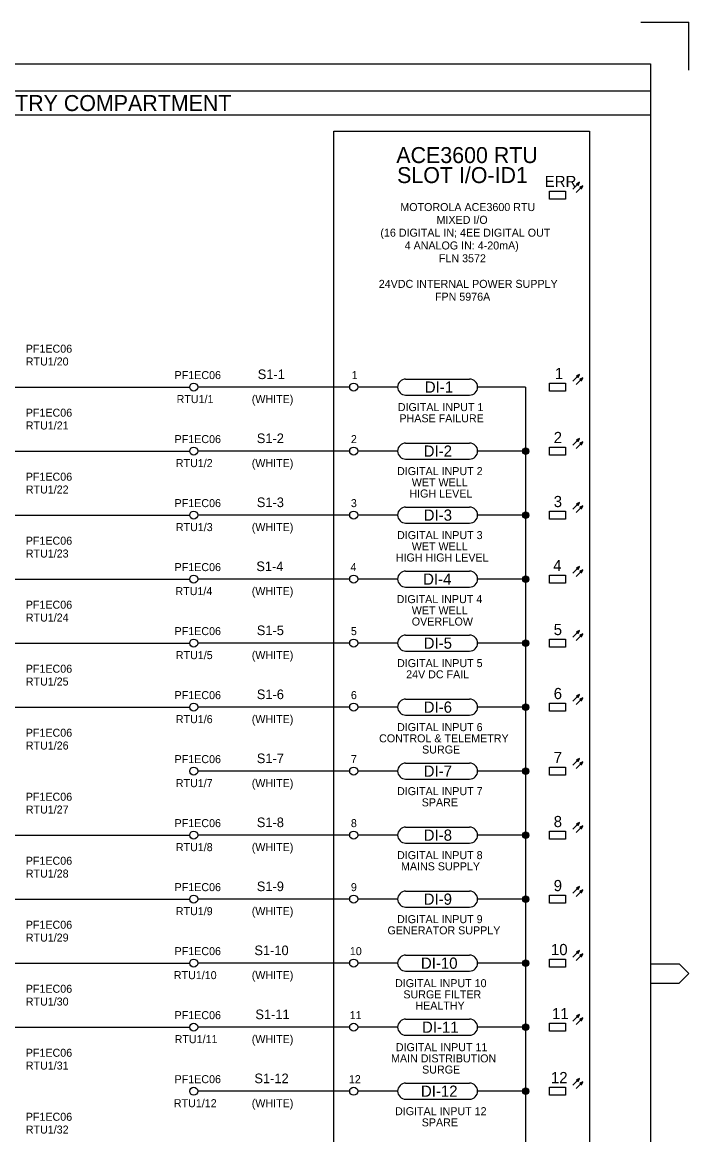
# Model space of a CAD drawing. Extents: x 0 to 841, y 0 to 594.
# Drawn here: x 632.6 to 841, y 246.4 to 594 of the extents above; entities that cross this region are included whole.
import ezdxf

# ---------------------------------------------------------------- set-up
doc = ezdxf.new("R2010")
doc.units = 0
for name, color, linetype in [('A1BORDER', 7, 'Continuous'), ('Level 1', 7, 'Continuous'), ('Level 10', 7, 'Continuous'), ('Level 2', 7, 'Continuous')]:
    doc.layers.add(name, color=color, linetype=linetype)

msp = doc.modelspace()

# ---------------------------------------------------------------- linework, layer by layer
at = {"layer": 'A1BORDER'}
for p, q in [((826, 594), (841, 594)), ((841, 579), (841, 594)), ((28, 581), (829, 581)), ((829, 581), (829, 15)), ((829, 299.76), (838, 299.76)), ((838, 299.76), (841, 296.76)), ((838, 293.76), (841, 296.76)), ((829, 293.76), (838, 293.76))]:
    msp.add_line(p, q, dxfattribs=at)
at = {"layer": 'Level 1'}
for p, q in [((829, 572.5), (160, 572.5)), ((829, 565), (160, 565)), ((530, 480), (685, 480)), ((735, 480), (687.5, 480)), ((750, 480), (737.5, 480)), ((752.5, 482.5), (772.5, 482.5)), ((790, 480), (775, 480)), ((790, 480), (790, 140)), ((752.5, 477.5), (772.5, 477.5)), ((752.5, 462.5), (772.5, 462.5)), ((280, 460), (685, 460)), ((735, 460), (687.5, 460)), ((750, 460), (737.5, 460)), ((790, 460), (775, 460)), ((752.5, 457.5), (772.5, 457.5)), ((752.5, 442.5), (772.5, 442.5)), ((280, 440), (685, 440)), ((735, 440), (687.5, 440)), ((750, 440), (737.5, 440)), ((790, 440), (775, 440)), ((752.5, 437.5), (772.5, 437.5)), ((752.5, 422.5), (772.5, 422.5)), ((280, 420), (685, 420)), ((735, 420), (687.5, 420)), ((750, 420), (737.5, 420)), ((752.5, 417.5), (772.5, 417.5)), ((790, 420), (775, 420)), ((530, 400), (685, 400)), ((735, 400), (687.5, 400)), ((750, 400), (737.5, 400)), ((752.5, 402.5), (772.5, 402.5)), ((790, 400), (775, 400)), ((752.5, 397.5), (772.5, 397.5)), ((752.5, 382.5), (772.5, 382.5)), ((415, 380), (685, 380)), ((735, 380), (687.5, 380)), ((750, 380), (737.5, 380)), ((790, 380), (775, 380)), ((752.5, 377.5), (772.5, 377.5)), ((752.5, 362.5), (772.5, 362.5)), ((735, 360), (687.5, 360)), ((750, 360), (737.5, 360)), ((790, 360), (775, 360)), ((752.5, 357.5), (772.5, 357.5)), ((752.5, 342.5), (772.5, 342.5)), ((360, 340), (685, 340)), ((735, 340), (687.5, 340)), ((750, 340), (737.5, 340)), ((752.5, 337.5), (772.5, 337.5)), ((790, 340), (775, 340)), ((360, 320), (685, 320)), ((735, 320), (687.5, 320)), ((750, 320), (737.5, 320)), ((752.5, 322.5), (772.5, 322.5)), ((790, 320), (775, 320)), ((752.5, 317.5), (772.5, 317.5)), ((752.5, 302.5), (772.5, 302.5)), ((480, 300), (685, 300)), ((735, 300), (687.5, 300)), ((750, 300), (737.5, 300)), ((790, 300), (775, 300)), ((752.5, 297.5), (772.5, 297.5)), ((752.5, 282.5), (772.5, 282.5)), ((325, 280), (685, 280)), ((735, 280), (687.5, 280)), ((750, 280), (737.5, 280)), ((790, 280), (775, 280)), ((752.5, 277.5), (772.5, 277.5)), ((752.5, 262.5), (772.5, 262.5)), ((735, 260), (687.5, 260)), ((750, 260), (737.5, 260)), ((752.5, 257.5), (772.5, 257.5)), ((790, 260), (775, 260))]:
    msp.add_line(p, q, dxfattribs=at)
msp.add_lwpolyline([(730, 96.05), (730, 560), (810, 560), (810, 103.95)], dxfattribs=at)
for points in [[(797.5, 541.25), (802.5, 541.25), (802.5, 538.75), (797.5, 538.75)], [(797.5, 481.25), (802.5, 481.25), (802.5, 478.75), (797.5, 478.75)], [(797.5, 461.25), (802.5, 461.25), (802.5, 458.75), (797.5, 458.75)], [(797.5, 441.25), (802.5, 441.25), (802.5, 438.75), (797.5, 438.75)], [(797.5, 421.25), (802.5, 421.25), (802.5, 418.75), (797.5, 418.75)], [(797.5, 401.25), (802.5, 401.25), (802.5, 398.75), (797.5, 398.75)], [(797.5, 381.25), (802.5, 381.25), (802.5, 378.75), (797.5, 378.75)], [(797.5, 361.25), (802.5, 361.25), (802.5, 358.75), (797.5, 358.75)], [(797.5, 341.25), (802.5, 341.25), (802.5, 338.75), (797.5, 338.75)], [(797.5, 321.25), (802.5, 321.25), (802.5, 318.75), (797.5, 318.75)], [(797.5, 301.25), (802.5, 301.25), (802.5, 298.75), (797.5, 298.75)], [(797.5, 281.25), (802.5, 281.25), (802.5, 278.75), (797.5, 278.75)], [(797.5, 261.25), (802.5, 261.25), (802.5, 258.75), (797.5, 258.75)]]:
    msp.add_lwpolyline(points, close=True, dxfattribs=at)
for centre, start, end in [((752.5, 480), 90, 270), ((772.5, 480), 270, 90), ((752.5, 460), 90, 270), ((772.5, 460), 270, 90), ((752.5, 440), 90, 270), ((772.5, 440), 270, 90), ((752.5, 420), 90, 270), ((772.5, 420), 270, 90), ((752.5, 400), 90, 270), ((772.5, 400), 270, 90), ((752.5, 380), 90, 270), ((772.5, 380), 270, 90), ((752.5, 360), 90, 270), ((772.5, 360), 270, 90), ((752.5, 340), 90, 270), ((772.5, 340), 270, 90), ((752.5, 320), 90, 270), ((772.5, 320), 270, 90), ((752.5, 300), 90, 270), ((772.5, 300), 270, 90), ((752.5, 280), 90, 270), ((772.5, 280), 270, 90), ((752.5, 260), 90, 270), ((772.5, 260), 270, 90)]:
    msp.add_arc(centre, 2.5, start, end, dxfattribs=at)
at = {"layer": 'Level 10'}
for p, q in [((804.73, 541.86), (806.86, 543.98)), ((805.79, 540.79), (807.91, 542.92)), ((805.96, 543.58), (806.67, 543.58)), ((806, 543.42), (806.61, 543.42)), ((806.14, 543.27), (806.53, 543.27)), ((806.29, 543.73), (806.74, 543.73)), ((806.3, 543.12), (806.47, 543.12)), ((806.62, 543.88), (806.81, 543.88)), ((807.02, 542.51), (807.73, 542.51)), ((807.06, 542.37), (807.66, 542.37)), ((807.35, 542.66), (807.8, 542.66)), ((807.68, 542.82), (807.87, 542.82)), ((807.21, 542.22), (807.6, 542.22)), ((807.36, 542.07), (807.53, 542.07)), ((804.73, 481.86), (806.86, 483.98)), ((805.96, 483.57), (806.67, 483.57)), ((806, 483.43), (806.61, 483.43)), ((806.14, 483.28), (806.53, 483.28)), ((806.29, 483.73), (806.74, 483.73)), ((806.62, 483.88), (806.81, 483.88)), ((805.79, 480.8), (807.91, 482.92)), ((806.3, 483.12), (806.47, 483.12)), ((807.02, 482.51), (807.73, 482.51)), ((807.06, 482.37), (807.66, 482.37)), ((807.21, 482.22), (807.6, 482.22)), ((807.35, 482.67), (807.8, 482.67)), ((807.36, 482.06), (807.53, 482.06)), ((807.68, 482.81), (807.87, 482.81)), ((804.73, 461.86), (806.86, 463.98)), ((805.79, 460.8), (807.91, 462.92)), ((805.96, 463.57), (806.67, 463.57)), ((806, 463.43), (806.61, 463.43)), ((806.14, 463.28), (806.53, 463.28)), ((806.29, 463.73), (806.74, 463.73)), ((806.3, 463.12), (806.47, 463.12)), ((806.62, 463.88), (806.81, 463.88)), ((807.02, 462.51), (807.73, 462.51)), ((807.06, 462.37), (807.66, 462.37)), ((807.35, 462.67), (807.8, 462.67)), ((807.68, 462.81), (807.87, 462.81)), ((789.01, 460.1), (790.99, 460.1)), ((789.02, 459.8), (790.98, 459.8)), ((789.08, 460.4), (790.92, 460.4)), ((789.13, 459.5), (790.87, 459.5)), ((789.29, 460.7), (790.71, 460.7)), ((789.4, 459.2), (790.6, 459.2)), ((790, 461), (790, 461)), ((807.21, 462.22), (807.6, 462.22)), ((807.36, 462.06), (807.53, 462.06)), ((804.73, 441.86), (806.86, 443.98)), ((805.79, 440.8), (807.91, 442.92)), ((805.96, 443.57), (806.67, 443.57)), ((806, 443.43), (806.61, 443.43)), ((806.14, 443.28), (806.53, 443.28)), ((806.29, 443.73), (806.74, 443.73)), ((806.3, 443.12), (806.47, 443.12)), ((806.62, 443.88), (806.81, 443.88)), ((807.02, 442.51), (807.73, 442.51)), ((807.06, 442.37), (807.66, 442.37)), ((807.21, 442.22), (807.6, 442.22)), ((807.35, 442.67), (807.8, 442.67)), ((807.36, 442.06), (807.53, 442.06)), ((807.68, 442.81), (807.87, 442.81)), ((789.01, 440.1), (790.99, 440.1)), ((789.02, 439.8), (790.98, 439.8)), ((789.08, 440.4), (790.92, 440.4)), ((789.13, 439.5), (790.87, 439.5)), ((789.29, 440.7), (790.71, 440.7)), ((789.4, 439.2), (790.6, 439.2)), ((790, 441), (790, 441)), ((789.29, 420.7), (790.71, 420.7)), ((790, 421), (790, 421)), ((804.73, 421.86), (806.86, 423.98)), ((805.79, 420.8), (807.91, 422.92)), ((805.96, 423.57), (806.67, 423.57)), ((806, 423.43), (806.61, 423.43)), ((806.14, 423.28), (806.53, 423.28)), ((806.29, 423.73), (806.74, 423.73)), ((806.3, 423.12), (806.47, 423.12)), ((806.62, 423.88), (806.81, 423.88)), ((807.02, 422.51), (807.73, 422.51)), ((807.06, 422.37), (807.66, 422.37)), ((807.21, 422.22), (807.6, 422.22)), ((807.35, 422.67), (807.8, 422.67)), ((807.36, 422.06), (807.53, 422.06)), ((807.68, 422.81), (807.87, 422.81)), ((789.01, 420.1), (790.99, 420.1)), ((789.02, 419.8), (790.98, 419.8)), ((789.08, 420.4), (790.92, 420.4)), ((789.13, 419.5), (790.87, 419.5)), ((789.4, 419.2), (790.6, 419.2)), ((804.73, 401.86), (806.86, 403.98)), ((805.96, 403.57), (806.67, 403.57)), ((806, 403.43), (806.61, 403.43)), ((806.14, 403.28), (806.53, 403.28)), ((806.29, 403.73), (806.74, 403.73)), ((806.62, 403.88), (806.81, 403.88)), ((789.01, 400.1), (790.99, 400.1)), ((789.02, 399.8), (790.98, 399.8)), ((789.08, 400.4), (790.92, 400.4)), ((789.29, 400.7), (790.71, 400.7)), ((790, 401), (790, 401)), ((805.79, 400.8), (807.91, 402.92)), ((806.3, 403.12), (806.47, 403.12)), ((807.02, 402.51), (807.73, 402.51)), ((807.06, 402.37), (807.66, 402.37)), ((807.21, 402.22), (807.6, 402.22)), ((807.35, 402.67), (807.8, 402.67)), ((807.36, 402.06), (807.53, 402.06)), ((807.68, 402.81), (807.87, 402.81)), ((789.13, 399.5), (790.87, 399.5)), ((789.4, 399.2), (790.6, 399.2)), ((804.73, 381.86), (806.86, 383.98)), ((805.79, 380.8), (807.91, 382.92)), ((805.96, 383.57), (806.67, 383.57)), ((806, 383.43), (806.61, 383.43)), ((806.14, 383.28), (806.53, 383.28)), ((806.29, 383.73), (806.74, 383.73)), ((806.3, 383.12), (806.47, 383.12)), ((806.62, 383.88), (806.81, 383.88)), ((807.02, 382.51), (807.73, 382.51)), ((807.35, 382.67), (807.8, 382.67)), ((807.68, 382.81), (807.87, 382.81)), ((789.01, 380.1), (790.99, 380.1)), ((789.02, 379.8), (790.98, 379.8)), ((789.08, 380.4), (790.92, 380.4)), ((789.13, 379.5), (790.87, 379.5)), ((789.29, 380.7), (790.71, 380.7)), ((789.4, 379.2), (790.6, 379.2)), ((790, 381), (790, 381)), ((807.06, 382.37), (807.66, 382.37)), ((807.21, 382.22), (807.6, 382.22)), ((807.36, 382.06), (807.53, 382.06)), ((804.73, 361.86), (806.86, 363.98)), ((805.79, 360.8), (807.91, 362.92)), ((805.96, 363.57), (806.67, 363.57)), ((806, 363.43), (806.61, 363.43)), ((806.14, 363.28), (806.53, 363.28)), ((806.29, 363.73), (806.74, 363.73)), ((806.3, 363.12), (806.47, 363.12)), ((806.62, 363.88), (806.81, 363.88)), ((807.02, 362.51), (807.73, 362.51)), ((807.06, 362.37), (807.66, 362.37)), ((807.21, 362.22), (807.6, 362.22)), ((807.35, 362.67), (807.8, 362.67)), ((807.36, 362.06), (807.53, 362.06)), ((807.68, 362.81), (807.87, 362.81)), ((789.01, 360.1), (790.99, 360.1)), ((789.02, 359.8), (790.98, 359.8)), ((789.08, 360.4), (790.92, 360.4)), ((789.13, 359.5), (790.87, 359.5)), ((789.29, 360.7), (790.71, 360.7)), ((789.4, 359.2), (790.6, 359.2)), ((790, 361), (790, 361)), ((789.29, 340.7), (790.71, 340.7)), ((790, 341), (790, 341)), ((804.73, 341.86), (806.86, 343.98)), ((805.79, 340.8), (807.91, 342.92)), ((805.96, 343.57), (806.67, 343.57)), ((806, 343.43), (806.61, 343.43)), ((806.14, 343.28), (806.53, 343.28)), ((806.29, 343.73), (806.74, 343.73)), ((806.3, 343.12), (806.47, 343.12)), ((806.62, 343.88), (806.81, 343.88)), ((807.02, 342.51), (807.73, 342.51)), ((807.06, 342.37), (807.66, 342.37)), ((807.21, 342.22), (807.6, 342.22)), ((807.35, 342.67), (807.8, 342.67)), ((807.36, 342.06), (807.53, 342.06)), ((807.68, 342.81), (807.87, 342.81)), ((789.01, 340.1), (790.99, 340.1)), ((789.02, 339.8), (790.98, 339.8)), ((789.08, 340.4), (790.92, 340.4)), ((789.13, 339.5), (790.87, 339.5)), ((789.4, 339.2), (790.6, 339.2)), ((804.73, 321.86), (806.86, 323.98)), ((805.96, 323.57), (806.67, 323.57)), ((806, 323.43), (806.61, 323.43)), ((806.29, 323.73), (806.74, 323.73)), ((806.62, 323.88), (806.81, 323.88)), ((789.01, 320.1), (790.99, 320.1)), ((789.08, 320.4), (790.92, 320.4)), ((789.29, 320.7), (790.71, 320.7)), ((790, 321), (790, 321)), ((805.79, 320.8), (807.91, 322.92)), ((806.14, 323.28), (806.53, 323.28)), ((806.3, 323.12), (806.47, 323.12)), ((807.02, 322.51), (807.73, 322.51)), ((807.06, 322.37), (807.66, 322.37)), ((807.21, 322.22), (807.6, 322.22)), ((807.35, 322.67), (807.8, 322.67)), ((807.36, 322.06), (807.53, 322.06)), ((807.68, 322.81), (807.87, 322.81)), ((789.02, 319.8), (790.98, 319.8)), ((789.13, 319.5), (790.87, 319.5)), ((789.4, 319.2), (790.6, 319.2)), ((804.73, 301.86), (806.86, 303.98)), ((805.79, 300.8), (807.91, 302.92)), ((805.96, 303.57), (806.67, 303.57)), ((806, 303.43), (806.61, 303.43)), ((806.14, 303.28), (806.53, 303.28)), ((806.29, 303.73), (806.74, 303.73)), ((806.3, 303.12), (806.47, 303.12)), ((806.62, 303.88), (806.81, 303.88)), ((807.02, 302.51), (807.73, 302.51)), ((807.35, 302.67), (807.8, 302.67)), ((807.68, 302.81), (807.87, 302.81)), ((789.01, 300.1), (790.99, 300.1)), ((789.02, 299.8), (790.98, 299.8)), ((789.08, 300.4), (790.92, 300.4)), ((789.13, 299.5), (790.87, 299.5)), ((789.29, 300.7), (790.71, 300.7)), ((789.4, 299.2), (790.6, 299.2)), ((790, 301), (790, 301)), ((807.06, 302.37), (807.66, 302.37)), ((807.21, 302.22), (807.6, 302.22)), ((807.36, 302.06), (807.53, 302.06)), ((804.73, 281.86), (806.86, 283.98)), ((805.79, 280.8), (807.91, 282.92)), ((805.96, 283.57), (806.67, 283.57)), ((806, 283.43), (806.61, 283.43)), ((806.14, 283.28), (806.53, 283.28)), ((806.29, 283.73), (806.74, 283.73)), ((806.3, 283.12), (806.47, 283.12)), ((806.62, 283.88), (806.81, 283.88)), ((807.02, 282.51), (807.73, 282.51)), ((807.06, 282.37), (807.66, 282.37)), ((807.21, 282.22), (807.6, 282.22)), ((807.35, 282.67), (807.8, 282.67)), ((807.36, 282.06), (807.53, 282.06)), ((807.68, 282.81), (807.87, 282.81)), ((789.01, 280.1), (790.99, 280.1)), ((789.02, 279.8), (790.98, 279.8)), ((789.08, 280.4), (790.92, 280.4)), ((789.13, 279.5), (790.87, 279.5)), ((789.29, 280.7), (790.71, 280.7)), ((789.4, 279.2), (790.6, 279.2)), ((790, 281), (790, 281)), ((790, 261), (790, 261)), ((804.73, 261.86), (806.86, 263.98)), ((805.79, 260.8), (807.91, 262.92)), ((805.96, 263.57), (806.67, 263.57)), ((806, 263.43), (806.61, 263.43)), ((806.14, 263.27), (806.53, 263.27)), ((806.29, 263.73), (806.74, 263.73)), ((806.3, 263.12), (806.47, 263.12)), ((806.62, 263.88), (806.81, 263.88)), ((807.02, 262.51), (807.73, 262.51)), ((807.06, 262.37), (807.66, 262.37)), ((807.21, 262.22), (807.6, 262.22)), ((807.35, 262.67), (807.8, 262.67)), ((807.36, 262.06), (807.53, 262.06)), ((807.68, 262.81), (807.87, 262.81)), ((789.01, 260.1), (790.99, 260.1)), ((789.02, 259.8), (790.98, 259.8)), ((789.08, 260.4), (790.92, 260.4)), ((789.13, 259.5), (790.87, 259.5)), ((789.29, 260.7), (790.71, 260.7)), ((789.4, 259.2), (790.6, 259.2))]:
    msp.add_line(p, q, dxfattribs=at)
for points in [[(806.86, 543.98), (805.88, 543.54), (806.41, 543)], [(807.91, 542.92), (806.94, 542.48), (807.48, 541.95)], [(806.86, 483.98), (805.88, 483.54), (806.41, 483)], [(807.91, 482.92), (806.94, 482.48), (807.48, 481.94)], [(806.86, 463.98), (805.88, 463.54), (806.41, 463)], [(807.91, 462.92), (806.94, 462.48), (807.48, 461.94)], [(806.86, 443.98), (805.88, 443.54), (806.41, 443)], [(807.91, 442.92), (806.94, 442.48), (807.48, 441.94)], [(806.86, 423.98), (805.88, 423.54), (806.41, 423)], [(807.91, 422.92), (806.94, 422.48), (807.48, 421.94)], [(806.86, 403.98), (805.88, 403.54), (806.41, 403)], [(807.91, 402.92), (806.94, 402.48), (807.48, 401.94)], [(806.86, 383.98), (805.88, 383.54), (806.41, 383)], [(807.91, 382.92), (806.94, 382.48), (807.48, 381.94)], [(806.86, 363.98), (805.88, 363.54), (806.41, 363)], [(807.91, 362.92), (806.94, 362.48), (807.48, 361.94)], [(806.86, 343.98), (805.88, 343.54), (806.41, 343)], [(807.91, 342.92), (806.94, 342.48), (807.48, 341.94)], [(806.86, 323.98), (805.88, 323.54), (806.41, 323)], [(807.91, 322.92), (806.94, 322.48), (807.48, 321.94)], [(806.86, 303.98), (805.88, 303.54), (806.41, 303)], [(807.91, 302.92), (806.94, 302.48), (807.48, 301.94)], [(806.86, 283.98), (805.88, 283.54), (806.41, 283)], [(807.91, 282.92), (806.94, 282.48), (807.48, 281.94)], [(806.86, 263.98), (805.88, 263.54), (806.41, 263)], [(807.91, 262.92), (806.94, 262.48), (807.48, 261.94)]]:
    msp.add_lwpolyline(points, close=True, dxfattribs=at)
for centre, radius in [((686.25, 480), 1.25), ((736.25, 480), 1.25), ((686.25, 460), 1.25), ((736.25, 460), 1.25), ((790, 460), 1), ((686.25, 440), 1.25), ((736.25, 440), 1.25), ((790, 440), 1), ((686.25, 420), 1.25), ((736.25, 420), 1.25), ((790, 420), 1), ((686.25, 400), 1.25), ((736.25, 400), 1.25), ((790, 400), 1), ((686.25, 380), 1.25), ((736.25, 380), 1.25), ((790, 380), 1), ((686.25, 360), 1.25), ((736.25, 360), 1.25), ((790, 360), 1), ((686.25, 340), 1.25), ((736.25, 340), 1.25), ((790, 340), 1), ((686.25, 320), 1.25), ((736.25, 320), 1.25), ((790, 320), 1), ((686.25, 300), 1.25), ((736.25, 300), 1.25), ((790, 300), 1), ((686.25, 280), 1.25), ((736.25, 280), 1.25), ((790, 280), 1), ((686.25, 260), 1.25), ((736.25, 260), 1.25), ((790, 260), 1)]:
    msp.add_circle(centre, radius, dxfattribs=at)

# ---------------------------------------------------------------- texts
at = {"layer": 'Level 1'}
for s, height, p in [('TELEMETRY COMPARTMENT', 5, (603.66, 566.25)), ('ACE3600 RTU', 5, (749.58, 550)), ('SLOT I/O-ID1', 5, (749.83, 543.75)), ('ERR', 3.5, (795.99, 542.5)), ('MOTOROLA ACE3600 RTU', 2.5, (750.83, 535)), ('MIXED I/O', 2.5, (762.16, 531)), ('(16 DIGITAL IN; 4EE DIGITAL OUT', 2.5, (744.6, 527)), ('4 ANALOG IN: 4-20mA)', 2.5, (752.19, 523)), ('FLN 3572', 2.5, (762.9, 519)), ('24VDC INTERNAL POWER SUPPLY', 2.5, (744.1, 511)), ('FPN 5976A', 2.5, (761.66, 507)), ('PF1EC06', 2.5, (680.27, 482.5)), ('S1-1', 3, (706.26, 482.5)), ('1', 2.5, (735.63, 482.5)), ('1', 3.5, (799.13, 482.5)), ('DI-1', 3.5, (758.49, 478.25)), ('RTU1/1', 2.5, (680.9, 475)), ('(WHITE)', 2.5, (704.39, 475)), ('PF1EC06', 2.5, (633.75, 470.75)), ('DIGITAL INPUT 1', 2.5, (750.05, 472.5)), ('RTU1/21', 2.5, (633.75, 466.75)), ('PHASE FAILURE', 2.5, (750.55, 469)), ('2', 3.5, (798.78, 462.5)), ('PF1EC06', 2.5, (680.27, 462.5)), ('S1-2', 3, (705.97, 462.5)), ('2', 2.5, (735.38, 462.5)), ('DI-2', 3.5, (758.14, 458.25)), ('RTU1/2', 2.5, (680.65, 455)), ('(WHITE)', 2.5, (704.39, 455)), ('PF1EC06', 2.5, (633.75, 450.75)), ('DIGITAL INPUT 2', 2.5, (749.8, 452.5)), ('RTU1/22', 2.5, (633.75, 446.75)), ('WET WELL', 2.5, (754.41, 449)), ('PF1EC06', 2.5, (680.27, 442.5)), ('S1-3', 3, (705.97, 442.5)), ('3', 2.5, (735.38, 442.5)), ('HIGH LEVEL', 2.5, (753.66, 445.5)), ('3', 3.5, (798.78, 442.5)), ('DI-3', 3.5, (758.14, 438.25)), ('RTU1/3', 2.5, (680.65, 435)), ('(WHITE)', 2.5, (704.39, 435)), ('DIGITAL INPUT 3', 2.5, (749.8, 432.5)), ('PF1EC06', 2.5, (633.75, 430.75)), ('WET WELL', 2.5, (754.41, 429)), ('RTU1/23', 2.5, (633.75, 426.75)), ('HIGH HIGH LEVEL', 2.5, (749.43, 425.5)), ('PF1EC06', 2.5, (680.27, 422.5)), ('S1-4', 3, (705.82, 422.5)), ('4', 2.5, (735.25, 422.5)), ('4', 3.5, (798.61, 422.5)), ('DI-4', 3.5, (757.97, 418.25)), ('RTU1/4', 2.5, (680.53, 415)), ('(WHITE)', 2.5, (704.39, 415)), ('DIGITAL INPUT 4', 2.5, (749.68, 412.5)), ('PF1EC06', 2.5, (633.75, 410.75)), ('WET WELL', 2.5, (754.41, 409)), ('RTU1/24', 2.5, (633.75, 406.75)), ('OVERFLOW', 2.5, (754.41, 405.5)), ('PF1EC06', 2.5, (680.27, 402.5)), ('S1-5', 3, (705.97, 402.5)), ('5', 2.5, (735.38, 402.5)), ('5', 3.5, (798.78, 402.5)), ('DI-5', 3.5, (758.14, 398.25)), ('RTU1/5', 2.5, (680.65, 395)), ('(WHITE)', 2.5, (704.39, 395)), ('PF1EC06', 2.5, (633.75, 390.75)), ('DIGITAL INPUT 5', 2.5, (749.8, 392.5)), ('RTU1/25', 2.5, (633.75, 386.75)), ('24V DC FAIL', 2.5, (752.66, 389)), ('6', 3.5, (798.78, 382.5)), ('PF1EC06', 2.5, (680.27, 382.5)), ('S1-6', 3, (705.97, 382.5)), ('6', 2.5, (735.38, 382.5)), ('DI-6', 3.5, (758.14, 378.25)), ('RTU1/6', 2.5, (680.65, 375)), ('(WHITE)', 2.5, (704.39, 375)), ('PF1EC06', 2.5, (633.75, 370.75)), ('DIGITAL INPUT 6', 2.5, (749.8, 372.5)), ('RTU1/26', 2.5, (633.75, 366.75)), ('CONTROL & TELEMETRY', 2.5, (744.2, 369)), ('PF1EC06', 2.5, (680.27, 362.5)), ('S1-7', 3, (705.97, 362.5)), ('7', 2.5, (735.38, 362.5)), ('SURGE', 2.5, (757.64, 365.5)), ('7', 3.5, (798.78, 362.5)), ('DI-7', 3.5, (758.14, 358.25)), ('RTU1/7', 2.5, (680.65, 355)), ('(WHITE)', 2.5, (704.39, 355)), ('DIGITAL INPUT 7', 2.5, (749.8, 352.5)), ('SPARE', 2.5, (757.52, 349)), ('PF1EC06', 2.5, (680.27, 342.5)), ('S1-8', 3, (705.97, 342.5)), ('8', 2.5, (735.38, 342.5)), ('8', 3.5, (798.78, 342.5)), ('DI-8', 3.5, (758.14, 338.25)), ('RTU1/8', 2.5, (680.65, 335)), ('(WHITE)', 2.5, (704.39, 335)), ('DIGITAL INPUT 8', 2.5, (749.8, 332.5)), ('MAINS SUPPLY', 2.5, (751.04, 329)), ('PF1EC06', 2.5, (680.27, 322.5)), ('S1-9', 3, (705.97, 322.5)), ('9', 2.5, (735.38, 322.5)), ('9', 3.5, (798.78, 322.5)), ('DI-9', 3.5, (758.14, 318.25)), ('RTU1/9', 2.5, (680.65, 315)), ('(WHITE)', 2.5, (704.39, 315)), ('DIGITAL INPUT 9', 2.5, (749.8, 312.5)), ('GENERATOR SUPPLY', 2.5, (746.81, 309)), ('10', 3.5, (797.91, 302.5)), ('PF1EC06', 2.5, (680.27, 302.5)), ('S1-10', 3, (705.22, 302.5)), ('10', 2.5, (735.05, 302.5)), ('DI-10', 3.5, (757.27, 298.25)), ('RTU1/10', 2.5, (680.03, 295)), ('(WHITE)', 2.5, (704.39, 295)), ('DIGITAL INPUT 10', 2.5, (749.18, 292.5)), ('SURGE FILTER', 2.5, (751.79, 289)), ('S1-11', 3, (705.52, 282.5)), ('HEALTHY', 2.5, (755.53, 285.5)), ('11', 3.5, (798.26, 282.5)), ('PF1EC06', 2.5, (680.27, 282.5)), ('11', 2.5, (735.01, 282.5)), ('DI-11', 3.5, (757.62, 278.25)), ('RTU1/11', 2.5, (680.28, 275)), ('(WHITE)', 2.5, (704.39, 275)), ('DIGITAL INPUT 11', 2.5, (749.43, 272.5)), ('MAIN DISTRIBUTION', 2.5, (747.93, 269)), ('SURGE', 2.5, (757.64, 265.5)), ('PF1EC06', 2.5, (680.27, 262.5)), ('S1-12', 3, (705.22, 262.5)), ('12', 2.5, (734.75, 262.5)), ('12', 3.5, (797.91, 262.5)), ('DI-12', 3.5, (757.27, 258.25)), ('RTU1/12', 2.5, (680.03, 255)), ('(WHITE)', 2.5, (704.39, 255)), ('DIGITAL INPUT 12', 2.5, (749.18, 252.5)), ('SPARE', 2.5, (757.52, 249))]:
    msp.add_text(s, height=height, dxfattribs=at).set_placement(p)
at = {"layer": 'Level 2'}
for s, p in [('PF1EC06', (633.75, 490.75)), ('RTU1/20', (633.75, 486.75)), ('PF1EC06', (633.75, 350.75)), ('RTU1/27', (633.75, 346.75)), ('PF1EC06', (633.75, 330.75)), ('RTU1/28', (633.75, 326.75)), ('PF1EC06', (633.75, 310.75)), ('RTU1/29', (633.75, 306.75)), ('PF1EC06', (633.75, 290.75)), ('RTU1/30', (633.75, 286.75)), ('PF1EC06', (633.75, 270.75)), ('RTU1/31', (633.75, 266.75)), ('PF1EC06', (633.75, 250.75)), ('RTU1/32', (633.75, 246.75))]:
    msp.add_text(s, height=2.5, dxfattribs=at).set_placement(p)

doc.saveas('drawing.dxf')
